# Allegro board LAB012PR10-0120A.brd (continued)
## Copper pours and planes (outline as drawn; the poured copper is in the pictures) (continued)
B+ on TOP (solid shape): 80.73,20.27 80.73,18.67 80.52,18.47 79.04,18.47 78.33,19.17 78.33,20.66 78.62,20.95 80.05,20.95
B+ on TOP (solid shape): 8.45,79.5 8.45,78.58 8.62,78.41 9.33,78.41 10.19,77.55 10.19,76.36 9.95,76.12 6.93,76.12 6.79,76.26 6.79,78.03 6.6,78.21 6.6,78.64 7.16,78.64 7.16,79.13 6.6,79.13 6.6,79.63 6.66,79.68 8.27,79.68
B+ on TOP (solid shape): outline of 233 points within 26.09,18.5 87.59,40.89
B+ on BOTTOM (solid shape): 57.73,25.76 57.73,16.43 57.66,16.36 53.78,16.36 52.97,17.17 52.97,26.66 53.35,27.03 56.46,27.03
B+ on BOTTOM (solid shape): 58.96,118.17 58.96,115.45 58.65,115.14 55.73,115.14 55.4,115.47 55.4,118.24 55.73,118.57 58.55,118.57
B+ on BOTTOM (solid shape): 172.9,48.32 172.9,46.03 172.4,45.52 170.11,45.52 169.86,45.78 169.86,48.32 170.36,48.82 172.4,48.82
B+ on BOTTOM (solid shape): 9.96,77.78 9.96,76.76 9.56,76.36 7.93,76.36 7.93,78.29 8.06,78.41 9.33,78.41
B+ on BOTTOM (solid shape): 48.32,25.8 48.32,22.15 47.81,21.65 45.52,21.65 44.86,22.31 44.86,25.72 45.21,26.06 48.05,26.06
B+ on BOTTOM (solid shape): 80.7,21.39 80.7,18.6 80.57,18.47 78.92,18.47 78.8,18.6 78.8,21.39 78.92,21.52 80.57,21.52
B+ on BOTTOM (solid shape): outline of 149 points within 84.18,34.98 172.68,71.52
B+ on BOTTOM (solid shape): outline of 200 points within 26.22,20.1 32.95,33.84
B+_1.05V on BOTTOM (solid shape): 177.35,54.41 177.35,53.93 177.55,53.73 179.1,53.73 179.25,53.57 179.25,52.38 179.63,52 179.63,50.22 179.51,50.09 177.6,50.09 177.58,50.12 177.58,51.62 176.61,52.58 173.67,52.58 172.83,51.74 172.83,50.93 172.75,50.86 170.87,50.86 170.77,50.96 170.77,52.43 170.94,52.6 171.64,52.6 173.47,54.44 177.32,54.44
BATT+ on TOP (solid shape): 25.33,30.92 25.33,25.33 24.95,24.95 21.14,24.95 20.38,25.71 20.38,30.66 20.5,30.79 21.14,30.79 21.65,31.3 24.95,31.3
BATT+ on BOTTOM (solid shape): 25.33,30.79 25.33,25.2 25.08,24.95 21.27,24.95 20.5,25.71 20.5,30.28 21.52,31.3 24.82,31.3
BATT+ on IN1 (solid shape): 24.57,30.79 24.57,25.46 24.06,24.95 21.14,24.95 20.38,25.71 20.38,30.66 20.5,30.79 21.14,30.79 21.65,31.3 24.06,31.3
BATT++ on TOP (solid shape): 19.87,30.66 19.87,25.33 19.36,24.82 16.06,24.82 15.17,25.71 13.77,25.71 13.65,25.84 13.65,30.15 13.9,30.41 16.69,30.41 17.07,30.79 19.74,30.79
BATT++ on BOTTOM (solid shape): 19.87,30.66 19.87,25.33 19.61,25.07 15.8,25.07 15.17,25.71 13.77,25.71 13.65,25.84 13.65,30.15 13.9,30.41 16.69,30.41 17.07,30.79 19.74,30.79
BATT++ on IN1 (solid shape): 19.87,30.66 19.87,25.33 19.36,24.82 16.06,24.82 15.17,25.71 13.77,25.71 13.65,25.84 13.65,30.15 13.9,30.41 16.69,30.41 17.07,30.79 19.74,30.79
BOOT1 on BOTTOM (solid shape): 58.35,42.09 58.35,40.7 59.37,39.68 59.75,39.68 59.87,39.55 59.87,38.79 59.75,38.66 59.49,38.66 57.33,40.82 57.33,42.09 57.46,42.22 58.22,42.22
BOOT2 on BOTTOM (solid shape): 66,41.97 66,40.29 64.5,38.79 63.58,38.79 63.4,38.61 63.28,38.61 63.2,38.69 63.2,39.58 63.29,39.67 64.03,39.67 64.04,39.65 64.55,39.65 65.16,40.26 65.16,41.05 64.73,41.48 64.73,42.19 64.85,42.32 65.64,42.32
BOOT_1.35V on BOTTOM (solid shape): 89.59,11.1 89.59,10.22 89.46,10.09 87.31,10.09 87.05,10.34 87.05,10.85 86.8,11.1 85.15,11.1 85.15,11.36 89.34,11.36
BST on BOTTOM (solid shape): 44.56,18.32 44.56,16.75 44.23,16.42 44.23,15.47 44.2,15.45 44.08,15.45 44.02,15.5 44.02,17.35 43.69,17.68 43.69,18.39 44.48,18.39
BST_1.05V on BOTTOM (solid shape): 182.81,52.13 182.81,51.36 182.68,51.24 181.92,51.24 181.29,50.6 180.4,50.6 180.27,50.73 180.27,51.11 181.41,52.25 182.68,52.25
BST_1.35V on BOTTOM (solid shape): 89.59,13.64 89.59,11.74 89.46,11.61 88.58,11.61 88.45,11.74 88.45,13.64 88.58,13.77 89.46,13.77
BST_3V on TOP (solid shape): 71.92,21.82 71.92,20.43 71.91,20.39 71.87,20.38 71.56,20.38 71.56,20.38 71.16,20.38 70.96,20.58 70.96,21.79 71.03,21.86 71.88,21.86
BST_5V on TOP (solid shape): 71.63,15.93 71.67,15.92 71.68,15.88 71.68,15.68 71.43,15.42 71.43,15.42 71.1,15.09 71.1,14.02 71.05,13.97 70.1,13.97 69.94,14.13 69.94,14.63 70.89,15.58 71.22,15.58 71.57,15.93
BST_+1.35VGPUP on BOTTOM (solid shape): 33.84,45.39 33.84,44.63 34.73,43.74 34.73,43.11 34.6,42.98 33.71,42.98 32.95,43.74 32.95,45.39 33.08,45.52 33.71,45.52
BST_CHGA on BOTTOM (solid shape): 44.58,19.71 44.58,19.13 44.56,19.11 41.92,19.11 41.89,19.13 41.89,19.77 41.94,19.82 44.48,19.82
CHG_B+ on TOP (solid shape): 47.67,34.99 47.67,30.99 46.88,30.2 44.46,30.2 44.13,30.54 44.13,32.57 43.87,32.82 38.28,32.82 37.52,32.06 37.52,30.79 37.27,30.54 36.89,30.54 36.76,30.66 36.76,37.77 37.14,38.16 44.51,38.16
CHG_B+ on BOTTOM (solid shape): 46.67,34.32 46.67,31.25 45.76,30.34 43.81,30.34 42.73,31.42 42.73,34.01 43.25,34.54 46.45,34.54
DCIN on BOTTOM (solid shape): 49.76,18.27 49.76,17.38 48.93,16.54 48.93,15.52 48.52,15.12 47.76,15.12 47.17,14.53 45.78,14.53 45.65,14.66 45.65,14.79 45.73,14.86 46.63,14.86 47.3,15.54 47.3,16.82 48.88,18.39 49.64,18.39
DH_1.35V on TOP (solid shape): 88.91,13.11 88.91,12.4 87.99,11.49 87.18,11.49 87.05,11.61 87.05,12.18 88.06,13.19 88.83,13.19
DH_1.35V on BOTTOM (solid shape): 88.19,12.12 88.19,11.61 88.07,11.49 85.15,11.49 85.15,11.74 86.92,11.74 87.43,12.25 88.07,12.25
DH_CHG on TOP (solid shape): 43.74,32.06 43.74,29.77 43.62,29.65 42.98,29.65 42.73,29.9 42.73,32.06 42.86,32.19 43.62,32.19
DH_CHG on BOTTOM (solid shape): 43.87,17.28 43.87,15.5 43.8,15.42 43.64,15.42 43.57,15.5 43.57,16.87 42.98,17.45 42.98,17.66 43.14,17.81 43.34,17.81
DH_CHG on IN1 (solid shape): 44,30.41 44,29.77 43.62,29.39 43.24,29.39 42.47,30.15 42.47,30.92 42.6,31.04 43.36,31.04
DH_CHG on IN1 (solid shape): 44.25,18.85 44.25,17.2 44,16.95 43.36,16.95 42.98,17.33 42.98,18.85 43.11,18.98 44.13,18.98
DL_1.35V on BOTTOM (solid shape): 88.45,21.01 88.45,20.12 88.32,19.99 87.43,19.99 87.31,20.12 87.31,21.01 87.43,21.14 88.32,21.14
DL_1.35V on BOTTOM (solid shape): 86.04,14.41 86.04,13.39 84.89,12.25 84.77,12.25 84.64,12.37 84.64,13.39 85.78,14.53 85.91,14.53
DL_1.35V on IN2 (solid shape): 86.16,14.41 86.16,14.03 85.4,13.26 85.02,13.26 84.89,13.39 84.89,14.03 85.53,14.66 85.91,14.66
DL_1.35V on IN2 (solid shape): 88.7,21.26 88.7,20.07 88.5,19.87 87.53,19.87 87.31,20.1 87.31,21.26 87.43,21.39 88.58,21.39
DL_CHG on TOP (solid shape): 36.43,25.74 36.43,24.48 36.23,24.28 35.12,24.28 34.82,24.58 34.82,25.68 35.05,25.91 36.26,25.91
DL_CHG on BOTTOM (solid shape): 41.71,16.46 41.71,15.8 42.22,15.3 42.53,15.3 42.6,15.22 42.6,15.04 42.53,14.96 41.41,14.96 41.06,15.31 41.06,15.57 41.09,15.7 41.06,15.83 41.06,16.44 41.23,16.62 41.56,16.62
DL_CHG on IN1 (solid shape): 36.63,25.84 36.63,24.57 36.28,24.21 35.36,24.21 35.34,24.19 34.98,24.19 34.6,24.57 34.6,25.71 34.98,26.09 36.38,26.09
DL_CHG on IN2 (solid shape): 41.97,17.02 41.97,15.3 41.84,15.17 41.08,15.17 40.98,15.27 40.98,15.3 40.82,15.45 40.82,17.07 41.05,17.3 41.69,17.3
DL_CHG on IN2 (solid shape): 36.53,24.85 36.53,24.36 36.05,23.88 36.05,23.27 35.87,23.09 34.78,23.09 34.63,23.25 34.63,24.85 34.8,25.02 34.88,25.02 34.93,25.07 36.3,25.07
DP_VSSR on TOP (solid shape): 75.49,86.29 75.49,85.84 75.49,85.83 75.48,85.82 75.39,85.63 75.48,85.44 75.49,85.42 75.49,85.4 75.49,85.31 75.49,84.2 75.49,84.19 75.48,84.17 75.42,84 75.48,83.83 75.49,83.82 75.49,83.8 75.49,81.46 75.48,81.44 75.47,81.43 75.34,81.21 75.47,80.99 75.48,80.98 75.49,80.96 75.49,79.3 75.49,79.27 75.47,79.26 75.37,79.05 75.47,78.84 75.49,78.82 75.49,78.8 75.49,78.16 75.24,77.91 72.45,77.91 72.36,78 72.33,78.07 72.35,78.14 72.35,78.49 71.99,78.5 71.92,78.47 71.85,78.5 71.81,78.54 71.81,78.92 71.94,79.05 72.29,79.05 73.01,79.05 73.21,79.05 73.46,79.3 73.46,81.46 73.21,81.72 72.45,81.72 72.32,81.59 72.32,81.21 72.19,81.08 72.09,81.08 71.68,81.08 71.56,81.21 71.56,82.22 71.81,82.48 71.81,84.89 72.45,85.53 72.45,86.42 72.57,86.54 75.24,86.54
EN_PCIE on BOTTOM (solid shape): 76.64,56.19 76.64,55.55 76.76,55.43 77.4,55.43 77.78,55.05 77.78,54.67 77.65,54.54 75.88,54.54 75.37,55.05 74.99,55.05 74.86,55.17 74.86,56.19 74.99,56.32 76.51,56.32
GPU_B+ on TOP (solid shape): 71.38,45.16 74.09,45.16 74.67,44.58 74.67,43.05 73.78,42.16 67.18,42.16 66.48,42.85 61.86,42.85 61.7,42.7 60.43,42.7 60.2,42.47 60.2,41.52 60.1,41.42 58.48,41.42 58.41,41.45 58.38,41.52 58.1,41.79 57.82,41.52 57.79,41.45 57.71,41.42 57.14,41.42 57.13,41.42 56.98,41.46 56.82,41.42 56.81,41.42 56.46,41.42 56.45,41.42 56.32,41.44 56.19,41.42 56.18,41.42 51.95,41.42 51.49,41.87 51.49,45.06 51.56,45.12 51.66,45.32 51.64,45.55 51.63,45.56 51.64,45.6 52.11,46.07 57.13,46.07 57.21,46.16 64.45,46.16 64.7,46.41 64.7,47.17 64.95,47.43 69.12,47.43
GPU_B+ on BOTTOM (solid shape): 66.2,45.92 66.2,44.49 65.69,43.97 57.21,43.97 56.95,44.23 56.95,45.9 57.21,46.16 65.97,46.16
INT-SPK-L+ on TOP (solid shape): 202.04,20.71 202.04,20.2 202.04,20.2 202.04,19.94 202.55,19.44 203.76,19.44 203.92,19.28 203.92,18.5 203.74,18.32 202.04,18.32 200.97,19.38 200.97,20.3 200.95,20.33 200.95,20.91 201.1,21.06 201.68,21.06
INT-SPK-L+ on BOTTOM (solid shape): 201.73,20.6 201.73,19.94 201.33,19.54 199.17,19.54 199.12,19.59 199.12,19.74 199.17,19.79 200.72,19.79 201.12,20.2 201.12,20.55 201.28,20.71 201.63,20.71
INT-SPK-L- on TOP (solid shape): 206.05,20.07 206.05,18.57 205.85,18.37 205.01,18.37 204.83,18.55 204.83,19.44 204.35,19.92 202.49,19.92 202.16,20.25 202.16,20.83 202.42,21.09 205.03,21.09
INT-SPK-L- on BOTTOM (solid shape): 203.87,20.76 203.87,20.3 203.66,20.1 202.9,20.1 201.94,19.13 201.48,19.13 201.43,19.18 199.17,19.18 199.12,19.23 199.12,19.36 199.14,19.38 201.38,19.38 202.11,20.12 202.11,20.4 202.62,20.91 203.71,20.91
INT-SPK-R+ on TOP (solid shape): 209.1,19.31 209.1,18.52 208.9,18.32 206.43,18.32 206.23,18.52 206.23,19.21 206.48,19.46 208.95,19.46
INT-SPK-R+ on BOTTOM (solid shape): 201.28,18.17 201.28,17.5 201.22,17.45 200.95,17.45 200.59,17.81 200.59,18.19 200.41,18.37 199.19,18.37 199.12,18.44 199.12,18.55 199.17,18.6 200.84,18.6
INT-SPK-R+ on IN2 (solid shape): 207.93,19.16 207.93,18.55 207.75,18.37 202.47,18.37 202.44,18.34 201.86,18.34 201.45,17.94 201.45,17.76 201.48,17.73 201.48,17.33 201.33,17.17 200.59,17.17 200.39,17.38 200.39,19.18 200.41,19.18 200.64,19.41 207.68,19.41
INT-SPK-R- on TOP (solid shape): 212.88,19.44 212.88,18.77 212.48,18.37 210.11,18.37 209.91,18.57 209.91,19.38 210.11,19.59 212.73,19.59
INT-SPK-R- on BOTTOM (solid shape): 202.44,18.01 202.44,16.95 202.29,16.79 201.99,16.79 201.81,16.97 201.81,17.89 200.92,18.77 199.17,18.77 199.12,18.83 199.12,18.95 199.17,19 201.1,19 201.15,19.05 201.4,19.05
INT-SPK-R- on IN2 (solid shape): 213.06,19.36 213.06,18.83 212.78,18.55 211.51,18.55 209.78,16.82 202.65,16.82 202.56,16.74 201.9,16.74 201.69,16.95 201.69,17.68 202.08,18.06 209.45,18.06 211.03,19.64 212.78,19.64
KB_BL_PWM on TOP (solid shape): 121.16,13.85 121.16,13.19 122.23,12.12 122.23,8.16 121.3,7.23 120.63,7.23 120.45,7.41 120.45,10.62 119.44,11.64 119.44,13.9 119.56,14.03 120.99,14.03
LG_3V on TOP (solid shape): 69.69,19.93 69.69,19.92 70.59,19.03 71.22,19.03 71.29,18.97 71.29,18.9 71.22,18.84 69.93,18.84 68.91,19.85 68.91,20.16 69.04,20.29 69.34,20.29
LG_5V on TOP (solid shape): 63.73,17.38 63.73,16.62 63.68,16.57 63.68,16.06 63.18,15.55 62.54,15.55 62.29,15.8 62.29,16.95 62.3,16.96 62.3,17.42 62.46,17.59 63.52,17.59
LG_5V on TOP (solid shape): 71.29,17.39 71.29,17.25 71.22,17.19 70.84,17.19 70.45,16.79 70.45,16.46 69.9,15.92 69.47,15.92 69.37,16.02 69.37,16.3 69.37,16.32 69.38,16.33 69.42,16.38 69.46,16.44 70.23,17.21 70.22,17.23 70.22,17.33 70.33,17.44 71.24,17.44
LG_5V on IN1 (solid shape): 70.54,16.82 70.54,16.31 69.65,15.42 69.4,15.42 69.02,15.8 69.02,16.06 70.03,17.07 70.29,17.07
LG_5V on IN1 (solid shape): 63.23,16.7 63.23,16.26 63.81,15.68 63.81,15.42 63.43,15.04 63.05,15.04 62.36,15.73 62.36,16.78 62.44,16.86 63.07,16.86
LG_+1.35VGPUP on TOP (solid shape): 41.51,49.37 41.51,48.78 41.31,48.57 39.88,48.57 39.68,48.77 39.68,49.59 39.81,49.71 41.17,49.71
LGATE on TOP (solid shape): 85.58,119 85.58,118.55 85.35,118.32 84.33,118.32 84.13,118.52 84.13,119.46 84.21,119.54 85.05,119.54
LGATE on TOP (solid shape): 73.25,112.78 73.25,112.58 72.05,111.39 72.05,111.22 72.02,111.18 71.3,111.18 71.27,111.22 71.27,111.91 72.18,112.83 73.2,112.83
LGATE on BOTTOM (solid shape): 85.4,118.93 85.4,117.91 85.27,117.78 84.38,117.78 84.26,117.91 84.26,119.05 84.38,119.18 85.15,119.18
LGATE1 on TOP (solid shape): 60.38,54.87 60.38,54.16 60.64,53.9 60.64,53.52 60.51,53.4 59.37,53.4 59.11,53.65 59.11,53.9 59.29,54.08 59.59,54.08 59.75,54.23 59.75,54.87 59.85,54.97 60.28,54.97
LGATE1 on BOTTOM (solid shape): 61.4,42.47 61.4,41.46 61.02,41.08 61.02,38.66 60.89,38.66 60.76,38.79 60.76,40.82 60.25,41.33 60.25,42.47 60.38,42.6 61.27,42.6
LGATE1 on IN2 (solid shape): 61.22,42.47 61.22,41.43 60.97,41.18 60.64,41.18 60.33,41.48 60.33,42.47 60.51,42.65 61.04,42.65
LGATE1 on IN2 (solid shape): 60.69,53.84 60.69,53.17 60.48,52.96 59.8,52.96 59.71,53.05 59.71,53.14 59.26,53.59 59.26,53.93 59.41,54.08 60.45,54.08
LGATE2 on TOP (solid shape): 62.79,48.68 62.79,48.24 63.07,47.96 63.07,47.63 62.95,47.5 62.06,47.5 61.91,47.65 61.91,48.62 62.02,48.73 62.74,48.73
LGATE2 on BOTTOM (solid shape): 62.92,42.6 62.92,40.7 62.29,40.06 62.29,38.79 62.16,38.66 62.03,38.79 62.03,40.31 62.29,40.57 62.29,41.46 61.78,41.97 61.78,42.6 61.91,42.73 62.79,42.73
LGATE2 on IN2 (solid shape): 63.07,48.02 63.07,47.35 62.9,47.17 61.78,47.17 61.65,47.3 61.65,47.91 62.02,48.29 62.81,48.29
LX_1.05V on BOTTOM (solid shape): 183.19,53.9 183.19,53.65 182.81,53.27 182.81,52.63 182.68,52.51 182.05,52.51 181.92,52.63 181.92,53.85 182.1,54.03 183.06,54.03
LX_1.05V on BOTTOM (solid shape): 179.63,47.81 180.65,46.79 180.65,44.51 180.02,43.87 176.59,43.87 175.57,42.85 173.41,42.85 173.16,43.11 173.16,44.38 173.67,44.89 174.94,44.89 176.9,46.85 177.54,46.85 178.49,47.81 178.49,48.95 179.63,48.95
LX_1.8VSP on BOTTOM (solid shape): 87.28,28.76 87.28,27.18 86.97,26.88 86.97,25.73 86.92,25.68 86.8,25.68 86.72,25.76 86.72,26.09 86.72,26.42 86.47,26.67 86.24,26.67 86.14,26.57 86.13,26.57 85.83,26.28 85.64,26.09 85.64,25.83 85.01,25.83 85.01,26.72 84.75,26.97 83.54,26.97 83.37,27.14 83.37,28.76 83.5,28.88 87.15,28.88
LX_3V on TOP (solid shape): 66.35,26.93 66.35,23.3 63.25,23.3 63.19,23.36 63.19,23.37 62.02,24.54 60.46,24.54 60.27,24.73 60.27,27.31 60.28,27.31 60.53,27.56 65.72,27.56
LX_3V on TOP (solid shape): 73.69,21.73 73.69,21.26 73.54,21.1 73.36,21.1 72.37,20.11 72.37,19.16 72.3,19.09 72.24,19.09 72.18,19.16 72.18,20.3 72.05,20.43 72.05,21.32 72.18,21.44 72.18,21.45 72.59,21.86 73.56,21.86
LX_3V on BOTTOM (solid shape): 65.33,26.4 65.33,21.14 65.21,21.01 61.14,21.01 60.61,21.54 60.61,26.64 60.86,26.89 64.85,26.89
LX_3V on IN1 (solid shape): 63.56,24.69 63.56,24.06 64.06,23.55 64.06,23.42 63.81,23.17 63.43,23.17 62.92,23.68 62.92,24.69 63.05,24.82 63.43,24.82
LX_3V on IN1 (solid shape): 72.56,21.63 72.56,20.43 72.43,20.3 72.08,20.3 71.73,20.65 71.73,21.38 71.44,21.67 71.44,21.95 71.7,22.2 71.99,22.2
LX_5V on TOP (solid shape): 72.37,17.07 72.37,15.91 72.56,15.73 72.56,14.94 72.33,14.71 72.33,14.18 72.21,14.05 71.42,14.05 71.3,14.17 71.3,15.04 72.11,15.85 72.11,16.99 72.22,17.1 72.35,17.1
LX_5V on TOP (solid shape): 65.69,15.32 65.69,13.64 65.72,13.62 65.72,13.14 65.59,13.01 65.33,13.01 65.21,12.88 65.21,10.85 64.32,9.96 61.52,9.96 59.52,11.97 59.52,13.92 59.75,14.15 61.14,14.15 61.22,14.08 61.22,12.04 61.4,11.87 62.67,11.87 62.85,12.04 62.85,12.63 63.3,13.08 63.3,15.3 63.3,15.3 63.43,15.42 65.59,15.42
LX_5V on BOTTOM (solid shape): outline of 87 points within 59.37,10.09 65.7,15.17
LX_5V on IN1 (solid shape): 72.81,15.79 72.81,14.39 72.45,14.03 71.94,14.03 71.54,14.42 71.54,15.73 71.8,15.98 72.62,15.98
LX_5V on IN1 (solid shape): 65.84,12.76 65.84,12.12 65.72,11.99 64.57,11.99 64.32,11.74 62.92,11.74 62.79,11.87 62.79,12.37 63.3,12.88 65.72,12.88
LX_CHG on TOP (solid shape): 42.22,31.81 42.22,29.9 42.98,29.14 42.98,25.46 42.73,25.2 37.39,25.2 37.01,25.58 37.01,29.39 38.92,31.3 38.92,31.93 39.05,32.06 41.97,32.06
LX_CHG on BOTTOM (solid shape): 42.09,31.55 42.09,29.9 42.73,29.27 42.73,23.73 42.2,23.19 38.77,23.19 37.88,24.08 37.88,24.79 37.9,24.82 37.9,30.28 38.54,30.92 40.24,30.92 41,31.68 41.97,31.68
LX_CHG on BOTTOM (solid shape): 42.78,18.27 42.78,17.43 43.44,16.77 43.44,15.5 43.39,15.45 43.26,15.45 43.19,15.52 43.19,16.44 43.08,16.54 42.75,16.54 41.87,17.43 41.87,18.29 41.92,18.34 42.7,18.34
LX_CHG on IN1 (solid shape): 43.24,16.82 43.24,16.57 42.98,16.31 42.47,16.31 41.33,17.45 41.33,18.22 41.46,18.34 41.71,18.34
LX_CHG on IN1 (solid shape): 42.65,29.67 42.65,27.31 42.73,27.23 42.73,25.2 42.47,24.95 41.33,24.95 41.2,25.07 41.05,25.07 40.72,25.4 40.72,29.04 40.47,29.29 38.59,29.29 37.98,29.9 37.98,31.07 38.16,31.25 41.08,31.25
LX_PCIE on TOP (solid shape): 76.64,59.49 76.64,57.36 76.38,57.1 74.53,57.1 74.1,56.67 74.1,55.17 73.97,55.05 72.7,55.05 72.45,55.3 72.45,55.58 71.15,56.87 71.15,59.21 71.68,59.75 76.38,59.75
LX_PCIE on BOTTOM (solid shape): 76.49,59.47 76.49,57.36 75.83,56.7 74.35,56.7 74.1,56.44 74.1,55.17 73.97,55.05 72.19,55.05 72.07,55.17 72.07,55.99 71.15,56.9 71.15,59.19 71.71,59.75 76.21,59.75
MIC_IN_R on IN2 (solid shape): 198.56,34.21 199.42,34.21 199.66,33.96 199.66,32.81 199.48,32.63 197.61,32.63 197.16,33.08 197.16,33.81 197.58,33.82 197.7,34.22 198.56,34.22
PACIN# on TOP (solid shape): 77.78,97.72 77.78,96.83 77.65,96.7 76.13,96.7 76,96.83 76,97.85 76.13,97.97 77.53,97.97
PCIE_B+ on BOTTOM (solid shape): 74.1,52.76 74.1,51.87 74.99,50.98 76.13,50.98 76.26,51.11 76.26,52.38 76.51,52.63 77.53,52.63 77.65,52.51 77.65,49.2 77.4,48.95 73.46,48.95 73.34,49.08 73.34,51.11 72.83,51.62 72.83,52.76 72.95,52.89 73.97,52.89
PHASE on TOP (solid shape): 74.22,111.69 74.22,111.05 74.1,110.93 72.95,110.93 72.83,110.8 72.45,110.8 72.32,110.67 71.29,110.67 71.25,110.71 71.25,110.89 71.29,110.93 72.07,110.93 72.95,111.82 74.1,111.82
PHASE on BOTTOM (solid shape): 79.94,118.29 79.94,117.91 79.69,117.66 79.05,117.66 78.29,116.9 77.78,116.9 77.65,117.02 77.65,117.4 78.8,118.55 79.69,118.55
PHASE on IN2 (solid shape): 78.86,117.91 78.86,117.53 78.1,116.77 77.84,116.77 77.46,117.15 78.35,118.04 78.73,118.04
PHASE on IN2 (solid shape): 73.46,111.92 73.46,111.56 72.7,110.8 72.45,110.8 72.32,110.93 72.32,111.71 72.7,112.09 73.29,112.09
PHASE1 on TOP (solid shape): 54.91,56.31 55.02,56.29 55.13,56.31 55.14,56.32 55.56,56.32 56.45,55.42 56.45,46.93 56.14,46.63 53.3,46.63 52.92,47.01 52.92,48.48 52.62,48.78 51.98,48.78 50.71,50.04 50.27,50.04 50.09,50.22 50.09,54.41 52,56.32 54.9,56.32
PHASE1 on BOTTOM (solid shape): 60,42.22 60,41.2 60.64,40.57 60.64,38.66 60.56,38.59 60.48,38.59 60.41,38.66 60.41,40.03 59.75,40.7 59.7,40.7 58.98,41.41 58.98,42.22 59.11,42.35 59.87,42.35
PHASE1 on BOTTOM (solid shape): outline of 186 points within 49.36,45.97 57.46,59.49
PHASE1 on IN2 (solid shape): 51.64,51.41 51.64,50.12 51.5,49.98 51.02,49.98 50.88,50.12 50.88,51.31 51.01,51.44 51.62,51.44
PHASE1 on IN2 (solid shape): 60,41.97 60,41.58 60.64,40.95 60.64,40.42 60.38,40.16 60.15,40.16 59.11,41.2 59.11,41.46 58.86,41.71 58.86,42.09 59.11,42.35 59.62,42.35
PHASE2 on TOP (solid shape): 71.56,54.74 71.56,52.51 71.56,52.5 71.56,50.92 71.87,50.61 73.48,50.61 73.58,50.51 73.58,49.31 73.49,49.22 73.22,49.22 73.21,49.22 71.56,49.22 70.53,48.19 66.35,48.19 66.1,48.44 66.1,49.72 65.6,50.22 64.93,50.22 64.7,50.45 64.7,54.46 65.23,55 71.3,55
PHASE2 on BOTTOM (solid shape): 64.19,42.22 64.19,41.08 63.68,40.57 63.35,40.57 62.67,39.88 62.67,38.66 62.41,38.66 62.41,39.93 63.05,40.57 63.05,42.22 63.18,42.35 64.06,42.35
PHASE2 on BOTTOM (solid shape): 63.89,59.49 63.92,59.48 63.94,59.44 63.94,58.76 63.94,56.29 64.7,56.29 64.7,58.76 64.7,59.44 64.71,59.48 64.75,59.49 65.84,59.49 68.89,56.44 68.89,56.42 69,56.17 69.25,56.06 69.27,56.06 69.53,55.81 71.05,55.81 71.3,55.55 71.3,48.92 71.2,48.82 65.17,48.82 64.73,49.27 64.73,53.57 64.57,53.73 62.48,53.73 62.29,53.92 62.29,59.36 62.41,59.49
PHASE2 on IN1 (solid shape): 64.32,41.58 64.32,41.33 63.56,40.57 63.3,40.57 62.92,40.95 62.92,41.2 63.68,41.97 63.94,41.97
PHASE2 on IN1 (solid shape): 71,49.22 71,48.67 70.87,48.54 69.48,48.54 69.41,48.61 69.41,49.29 69.49,49.37 70.85,49.37
PWR_SRC_ON on TOP (solid shape): 10.09,75.87 10.09,75.44 9.99,75.34 9.33,75.34 9.18,75.19 9.18,73.87 8.87,73.56 7.02,73.56 6.76,73.82 6.76,75.67 7.07,75.98 9.99,75.98
RING2_R on IN2 (solid shape): 197.74,32.11 197.74,31.12 197.67,31.04 196.4,31.04 196.07,31.37 196.07,32.85 196.14,32.92 196.93,32.92
RING2_R on IN2 (solid shape): 200.42,38.36 203.18,38.36 203.33,38.51 207.82,38.51 208.04,38.4 208.27,38.37 209.42,38.37 210.39,37.39 210.39,36.73 210.27,36.61 208.69,36.61 208.69,36.63 208.11,37.22 208.11,37.22 207.98,37.34 206.75,37.34 206.55,37.48 206.3,37.53 205.39,37.53 205.14,37.48 204.94,37.34 202.65,37.34 202.45,37.48 202.2,37.53 201.29,37.53 201.04,37.48 200.84,37.34 199.55,37.34 199.35,37.55 199.35,38.59 199.45,38.69 200.09,38.69
SNB_1.05V on BOTTOM (solid shape): 175.32,46.66 175.32,45.65 175.19,45.52 173.41,45.52 173.16,45.78 173.16,47.55 173.28,47.68 174.3,47.68
SNUB_PCIE on TOP (solid shape): 76.64,56.48 76.64,54.7 76.51,54.58 76.24,54.58 76.12,54.7 76.12,55.31 75.88,55.55 74.73,55.55 74.61,55.68 74.61,56.57 74.76,56.72 75.09,56.72 75.1,56.74 76.38,56.74
SPK_L1-_CONN on TOP (solid shape): 205.97,17.81 205.97,15.7 206.23,15.45 206.23,15.07 205.9,14.74 205.44,14.74 204.88,15.3 204.88,17.86 204.93,17.91 205.87,17.91
SPK_L1-_CONN on BOTTOM (solid shape): 206.18,19.36 206.18,15.68 206.56,15.3 206.56,13.26 206.3,13.01 205.92,13.01 205.67,13.26 205.67,14.91 205.03,15.55 205.03,18.22 204.78,18.47 204.78,19.61 205.03,19.87 205.67,19.87
SPK_L2+_CONN on TOP (solid shape): 203.97,17.81 203.97,15.24 204.53,14.69 204.53,14.03 204.25,13.75 203.82,13.75 202.85,14.71 202.85,17.84 202.93,17.91 203.87,17.91
SPK_L2+_CONN on BOTTOM (solid shape): 204.02,19.49 204.02,18.47 203.76,18.22 203.76,15.68 204.4,15.04 205.03,15.04 205.29,14.79 205.29,13.26 205.03,13.01 204.65,13.01 202.62,15.04 202.62,19.23 203.26,19.87 203.64,19.87
SPK_R1-_CONN on TOP (solid shape): 211.11,17.81 211.11,16.87 211.08,16.85 211.08,16.03 211.11,16.01 211.11,15.7 211.33,15.47 211.33,14.08 211,13.75 210.52,13.75 209.96,14.3 209.96,17.86 210.04,17.94 210.98,17.94
SPK_R1-_CONN on BOTTOM (solid shape): 211,19.61 211,18.72 211.38,18.34 211.38,14.66 209.73,13.01 208.34,13.01 208.21,13.14 208.21,14.66 208.46,14.91 209.73,14.91 210.37,15.55 210.37,17.45 209.73,18.09 209.73,19.36 210.11,19.74 210.88,19.74
SPK_R2+_CONN on TOP (solid shape): 208.97,17.91 208.97,15.63 208.26,14.91 207.45,14.91 207.22,15.14 207.22,15.65 207.63,16.06 207.63,16.97 207.63,17.91 207.7,17.99 208.9,17.99
SPK_R2+_CONN on BOTTOM (solid shape): 209.1,19.49 209.1,17.96 208.72,17.58 208.72,15.68 207.83,14.79 207.83,13.39 207.45,13.01 207.19,13.01 206.94,13.26 206.94,15.3 207.57,15.93 207.57,17.96 207.96,18.34 207.96,19.49 208.21,19.74 208.84,19.74
SW_1.35V on BOTTOM (solid shape): 87.81,13.52 87.81,12.76 87.69,12.63 87.43,12.63 86.67,11.87 85.15,11.87 85.15,12.25 85.65,12.25 87.05,13.64 87.69,13.64
SW_1.35V on BOTTOM (solid shape): 94.8,20.63 94.8,15.93 93.86,14.99 90.4,14.99 90.4,14.99 90.36,14.99 90.04,15.31 90.04,17.08 89.03,18.09 89.03,21.98 89.21,22.15 93.27,22.15
SW_1.35V on IN2 (solid shape): 91.52,17.63 91.52,16.59 86.8,11.87 86.29,11.87 86.16,11.99 86.16,13.52 86.35,13.71 87.06,13.71 90.33,16.97 90.33,17.35 90.73,17.76 91.4,17.76
SW_+1.35VGPUP on TOP (solid shape): 37.78,51.49 37.78,50.86 39.17,49.46 39.17,46.66 39.43,46.41 40.7,46.41 41.08,46.03 41.08,44 40.95,43.87 39.3,43.87 38.28,44.89 37.14,44.89 37.01,45.01 37.01,46.03 36.76,46.28 36.63,46.28 36.63,47.83 35.58,48.88 35.58,50.91 36.12,51.45 36.12,51.49 36.38,51.74 37.52,51.74
SW_+1.35VGPUP on BOTTOM (solid shape): 40.82,47.68 40.82,43.87 39.81,42.85 37.01,42.85 36.63,43.24 36.63,45.14 36.38,45.39 35.36,45.39 34.6,46.16 32.95,46.16 32.95,46.54 36.25,46.54 36.63,46.92 36.63,47.55 37.27,48.19 40.32,48.19
SW_CPU2 on TOP (solid shape): 90.73,118.8 90.73,113.06 90.53,112.86 85.4,112.86 85.1,113.16 85.1,116.97 86.04,117.91 86.04,119.69 86.29,119.94 89.59,119.94
SW_CPU2 on BOTTOM (solid shape): 87.25,120.02 87.43,119.97 87.62,120.02 89.52,120.02 90.73,118.8 90.73,116.39 88.4,116.39 88.4,115.63 90.73,115.63 90.73,112.42 90.25,111.94 84.56,111.94 84.26,112.25 84.26,116.9 84.51,117.15 85.27,117.15 86.04,117.91 86.04,119.84 86.21,120.02
SW_CPU2 on IN1 (solid shape): 90.73,118.8 90.73,111.82 90.23,111.31 84.64,111.31 84.26,111.69 84.26,116.9 84.51,117.15 85.27,117.15 86.04,117.91 86.04,119.69 86.29,119.94 89.59,119.94
SW_CPU2 on IN2 (solid shape): 90.73,118.8 90.73,116.39 88.4,116.39 88.4,115.63 90.73,115.63 90.73,111.82 90.23,111.31 84.64,111.31 84.26,111.69 84.26,116.9 84.51,117.15 85.27,117.15 86.04,117.91 86.04,119.69 86.29,119.94 89.59,119.94
UG_3V on TOP (solid shape): 60.1,25.48 60.1,24.72 59.91,24.53 59.18,24.53 59.09,24.63 59.09,25.54 59.21,25.67 59.91,25.67
UG_3V on TOP (solid shape): 70.97,20.11 71.48,20.11 71.48,20.11 71.53,20.11 71.58,20.06 71.58,19.14 71.53,19.09 71.43,19.09 71.37,19.16 70.84,19.16 70.06,19.94 70.06,20.21 70.33,20.49 70.59,20.49
UG_3V on IN1 (solid shape): 71.29,19.96 71.29,19.36 71.15,19.22 70.88,19.22 69.32,20.78 69.32,20.95 69.75,21.38 69.87,21.38
UG_3V on IN1 (solid shape): 59.91,25.68 59.91,23.71 59.75,23.55 58.98,23.55 58.83,23.71 58.83,25.74 59.02,25.93 59.65,25.93
UG_5V on TOP (solid shape): 71.63,17.06 71.63,16.17 71.19,15.73 70.87,15.73 70.7,15.9 70.7,16.85 70.91,17.06 71.28,17.06 71.35,17.14 71.56,17.14
UG_5V on TOP (solid shape): 62.67,13.9 62.67,12.25 62.54,12.12 61.55,12.12 61.44,12.23 61.44,13.94 61.52,14.03 62.54,14.03
UG_5V on IN1 (solid shape): 71.35,16.74 71.35,15.09 71.19,14.93 70.75,14.93 70.51,15.16 70.51,15.84 70.72,16.04 70.72,16.93 70.78,17 71.1,17
UG_5V on IN1 (solid shape): 62.95,13.34 62.95,13.14 62.67,12.86 62.67,12.25 62.54,12.12 62.36,12.12 62.36,12.12 61.73,12.12 61.72,12.12 61.58,12.12 61.47,12.22 61.47,13.39 61.72,13.64 62.65,13.64
UG_+1.35VGPUP on TOP (solid shape): 36.76,45.9 36.76,45.01 36.63,44.89 34.35,44.89 34.09,45.14 34.09,45.9 34.22,46.03 36.63,46.03
UG_+1.35VGPUP on BOTTOM (solid shape): 34.85,45.52 34.85,45.14 34.6,44.89 34.35,44.89 34.09,45.14 34.09,45.39 33.84,45.65 33.08,45.65 32.95,45.78 32.95,46.03 34.35,46.03
UGATE on TOP (solid shape): 73.46,110.67 73.46,110.42 73.12,110.08 72.28,110.08 72.19,110.16 71.3,110.16 71.27,110.2 71.27,110.38 71.3,110.42 72.35,110.42 72.47,110.55 72.83,110.55 73.08,110.8 73.34,110.8
UGATE on BOTTOM (solid shape): 74.28,110.9 74.28,110.14 74.17,110.04 73.08,110.04 72.74,109.7 72.03,109.7 71.95,109.78 71.95,110.38 72.12,110.55 72.57,110.55 72.95,110.93 74.25,110.93
UGATE1 on TOP (solid shape): 50.98,48.06 50.98,46.28 50.73,46.03 50.22,46.03 49.97,46.28 49.97,48.19 50.09,48.32 50.73,48.32
UGATE1 on BOTTOM (solid shape): 60.25,39.93 60.25,38.66 60.18,38.59 60.08,38.59 60,38.66 60,39.81 59.87,39.93 59.37,39.93 58.48,40.82 58.48,41.08 58.6,41.2 58.98,41.2
UGATE1 on IN2 (solid shape): 51.06,47.76 51.06,46.05 51.01,46 50.39,46 50.12,46.27 50.12,47.76 50.2,47.83 50.98,47.83
UGATE1 on IN2 (solid shape): 58.98,41.33 58.98,41.08 59.49,40.57 59.49,40.31 59.34,40.16 58.83,40.16 57.97,41.03 57.97,41.2 58.48,41.71 58.6,41.71
UGATE2 on TOP (solid shape): 64.95,47.91 64.95,47.61 64.85,47.5 64.22,47.5 64.22,47.5 63.79,47.5 63.63,47.65 63.63,47.93 63.44,48.12 63.44,48.66 63.48,48.7 64.17,48.7
UGATE2 on BOTTOM (solid shape): 65,40.72 65,40.44 64.42,39.86 64.01,39.86 63.96,39.91 63.3,39.91 63.05,39.65 63.05,38.64 63,38.59 62.85,38.59 62.79,38.64 62.79,39.76 63.43,40.39 63.79,40.39 64.32,40.92 64.8,40.92
UGATE2 on IN2 (solid shape): 65,40.57 65,40.36 64.4,39.76 64.04,39.76 63.73,40.06 63.73,40.26 63.89,40.42 63.94,40.42 64.4,40.87 64.7,40.87
VSMB on BOTTOM (solid shape): 44.82,10.03 44.82,9.43 44.71,9.33 44.18,9.33 44,9.15 44,8.13 43.4,7.54 42.17,7.54 42.04,7.66 42.04,8.28 42.1,8.44 42.09,8.6 42.86,9.36 43.39,9.36 43.55,9.53 43.55,10.09 43.63,10.16 44.68,10.16
N16955074 on TOP (solid shape): 59.49,54.79 59.49,54.26 59.44,54.21 58.87,54.21 58.65,53.99 58.65,52.95 58.31,52.62 57.36,52.62 57.11,52.87 57.11,54.79 57.26,54.94 59.34,54.94
N16955074 on BOTTOM (solid shape): 59.2,49.72 59.2,49.02 59.01,48.84 57.28,48.84 57.19,48.93 57.19,49.59 57.32,49.71 58.55,49.71 58.76,49.92 59,49.92
N16955074 on IN1 (solid shape): 58.51,54.37 58.51,53.43 58.38,53.29 56.82,53.29 56.68,53.43 56.68,54.28 56.94,54.54 58.34,54.54
N16955074 on IN1 (solid shape): 58.37,50.01 58.9,50.01 59.09,49.81 59.09,48.96 58.94,48.8 57.93,48.8 57.46,49.28 57.46,50.1 57.57,50.22 58.16,50.22
N16955100 on BOTTOM (solid shape): 55.52,47.96 55.52,46.8 55.75,46.58 56.64,46.58 56.7,46.51 56.7,45.81 56.65,45.76 54.59,45.76 54.27,46.08 54.27,48.07 54.31,48.11 55.37,48.11
N16955117 on BOTTOM (solid shape): 60,43.46 60,42.83 59.92,42.75 57.49,42.75 57.36,42.88 57.36,43.49 57.41,43.54 59.92,43.54
N16955207 on TOP (solid shape): 52.07,48.44 52.51,48.44 52.61,48.34 52.61,46.63 52.49,46.52 51.85,46.52 51.29,47.08 51.29,48.01 50.73,48.57 50.22,48.57 50.09,48.7 50.09,49.33 50.35,49.59 50.92,49.59
N16988653 on BOTTOM (solid shape): 83.86,24.88 83.86,23.67 84.12,23.42 85.64,23.42 85.77,23.29 85.77,23.3 86.54,23.3 86.72,23.47 86.72,24.26 86.75,24.29 86.92,24.29 86.98,24.24 86.98,23.02 85.98,22.02 82.21,22.02 82.02,22.21 82.02,23.04 82.58,23.04 82.59,23.05 82.59,24.41 82.02,24.41 82.02,24.56 82.02,25.01 82.15,25.13 83.61,25.13
N17087943 on BOTTOM (solid shape): 66.1,36.38 66.1,36.12 65.84,35.87 65.59,35.87 65.21,35.49 63.56,35.49 63.43,35.62 63.43,36.5 63.52,36.59 63.54,36.6 63.56,36.61 63.61,36.6 64.42,36.6 64.47,36.61 64.53,36.63 65.84,36.63
N17089248 on BOTTOM (solid shape): 65.33,38.16 65.33,37.78 65.33,37.74 65.3,37.7 65.12,37.52 63.56,37.52 63.43,37.65 63.43,38.03 63.56,38.16 64.83,38.16 64.95,38.28 65.21,38.28
N17258399 on TOP (solid shape): 23.22,116.31 23.22,115.7 25.08,113.85 26.85,113.85 27.33,113.37 27.33,111.81 27.18,111.66 24.03,111.66 22.23,113.47 20.15,113.47 19.74,113.87 19.74,116.44 20.22,116.92 22.61,116.92
N17283470 on TOP (solid shape): 91.4,14 91.4,13.69 90.28,12.58 89.34,12.58 89.31,12.6 89.31,13.31 90.2,14.2 91.19,14.2
N17283470 on BOTTOM (solid shape): 91.37,14.66 91.37,13.64 91.24,13.52 90.1,13.52 89.97,13.64 89.97,14.53 90.23,14.79 91.24,14.79
N17446326 on BOTTOM (solid shape): 37.52,39.04 37.52,38.39 37.52,38.38 36.15,38.38 35.79,38.03 36.15,37.67 37.47,37.67 37.51,37.66 37.52,37.62 37.52,37.01 37.65,36.89 40.06,36.89 40.19,36.76 40.19,35.74 40.06,35.62 34.85,35.62 34.6,35.36 34.6,34.35 34.35,34.09 32.14,34.09 31.76,34.47 31.76,37.03 31.77,37.13 31.76,37.22 31.76,38.92 32.01,39.17 37.39,39.17
N17446342 on BOTTOM (solid shape): 26.71,42.03 26.71,41.56 26.46,41.3 26.46,39.51 26.8,39.17 26.8,38.03 27.06,37.77 29.98,37.77 30.36,37.39 30.36,34.22 30.23,34.09 29.07,34.09 28.72,34.4 28.37,34.09 27.44,34.09 27.18,34.35 27.18,35.23 26.93,35.49 24.95,35.49 24.69,35.74 24.69,38.66 25.71,39.68 25.71,41.95 25.84,42.08 26.66,42.08
N17613161 on BOTTOM (solid shape): 180.27,51.74 180.14,51.62 180.14,50.09 179.76,50.09 179.76,52.13 179.51,52.38 179.51,55.17 179.63,55.3 180.27,55.3
N17613228 on BOTTOM (solid shape): 184.21,53.52 184.21,51.36 184.08,51.24 183.44,51.24 183.32,51.36 183.32,53.52 183.44,53.65 184.08,53.65
N17933209 on TOP (solid shape): 62.73,50.98 63.87,50.98 63.96,50.89 63.96,50.34 63.82,50.2 63.38,50.2 62.91,49.73 62.91,49.24 62.75,49.08 62.15,49.08 62.01,49.21 62.01,50.7 61.96,50.75 61.96,51.18 62.05,51.27 62.45,51.27
N17933209 on BOTTOM (solid shape): 63.98,53.37 63.98,52.85 63.86,52.73 63.13,52.73 62.74,52.34 62.07,52.34 62,52.41 62,53.42 62.09,53.51 62.19,53.51 62.2,53.52 63.83,53.52
N17933209 on IN2 (solid shape): 63.08,53.46 63.08,52.35 62.93,52.19 62.17,52.19 62.03,52.33 62.03,53.38 62.26,53.6 62.94,53.6
N17933209 on IN2 (solid shape): 63.1,50.86 63.1,49.78 62.97,49.65 62.12,49.65 61.99,49.79 61.99,50.83 62.06,50.91 63.05,50.91
N17933219 on TOP (solid shape): 74.86,48.7 74.86,47.92 74.78,47.85 74.09,47.85 73.51,47.27 73.51,46.58 73.42,46.49 71.81,46.49 71.7,46.6 71.7,47.9 71.76,47.96 72.99,47.96 73.83,48.8 74.76,48.8
N17933234 on BOTTOM (solid shape): 65.72,43.62 65.72,42.98 65.59,42.85 63.18,42.85 63.05,42.98 63.05,43.62 63.18,43.74 65.59,43.74
N17933249 on TOP (solid shape): 65.72,49.38 65.72,48.29 65.59,48.16 65.06,48.16 64.67,48.54 64.67,48.9 64.55,49.03 63.48,49.03 63.4,49.1 63.4,49.59 63.51,49.69 63.51,49.69 63.58,49.76 65.34,49.76
N21178712 on TOP (solid shape): 35.74,111.18 35.74,108.64 35.49,108.39 34.22,108.39 34.09,108.51 34.09,109.15 33.71,109.53 32.19,109.53 32.06,109.66 32.06,111.18 32.26,111.38 35.55,111.38
N22753332 on BOTTOM (solid shape): 76.76,110.55 76.76,110.29 76.51,110.04 74.61,110.04 74.56,110.09 74.56,110.62 74.66,110.72 75.55,110.72 75.75,110.93 75.76,110.93 75.88,111.05 76.26,111.05
N22753332 on BOTTOM (solid shape): 79.94,117.02 79.94,116.51 79.81,116.39 79.3,116.39 78.42,115.5 78.03,115.5 77.91,115.63 77.91,116.01 79.05,117.15 79.81,117.15
N22753332 on IN2 (solid shape): 76.76,110.55 76.76,110.29 76.51,110.04 75.75,110.04 75.62,110.16 75.62,110.93 75.75,111.05 76.26,111.05
N22753332 on IN2 (solid shape): 78.92,116.45 78.92,115.94 78.42,115.43 78.16,115.43 77.91,115.69 77.91,115.94 78.54,116.58 78.8,116.58
N22753389 on TOP (solid shape): 75.75,111.69 75.75,111.05 75.49,110.8 75.49,109.02 75.39,108.92 74.71,108.92 74.48,109.15 74.48,111.43 74.86,111.82 75.62,111.82
N22763755 on TOP (solid shape): 18.6,37.39 18.6,36.12 18.34,35.87 15.68,35.87 15.55,36 15.55,37.27 15.68,37.39 16.19,37.39 16.31,37.52 18.47,37.52
N22763755 on BOTTOM (solid shape): 18.85,37.52 18.85,35.62 18.73,35.49 17.33,35.49 17.07,35.74 17.07,37.65 17.2,37.77 18.6,37.77
N22763812 on BOTTOM (solid shape): 21.52,24.31 21.52,22.15 21.39,22.03 19.74,22.03 19.61,22.15 19.61,24.69 19.74,24.82 21.01,24.82
N22763935 on BOTTOM (solid shape): 41.84,33.46 41.84,32.19 41.59,31.93 39.17,31.93 39.05,32.06 39.05,33.46 39.3,33.71 41.59,33.71
N22764304 on BOTTOM (solid shape): 46.54,39.04 46.54,36.38 46.03,35.87 41.97,35.87 40.7,37.14 38.79,37.14 38.54,37.39 38.54,37.67 39.91,37.67 40.27,38.03 39.91,38.38 38.64,38.38 38.64,39.4 38.92,39.68 45.9,39.68
N22892968 on TOP (solid shape): 74.13,109.87 74.13,108.92 74.1,108.89 73.43,108.89 72.7,109.62 71.27,109.62 71.21,109.68 71.21,109.88 71.26,109.93 74.07,109.93
N23711299 on TOP (solid shape): 207.09,11.8 207.13,11.79 207.14,11.75 207.14,9.14 207.46,8.82 209.24,8.82 209.43,8.63 209.43,5.19 209.28,5.04 208.53,5.04 207.74,5.83 206.88,5.83 206.84,5.85 206.83,5.88 206.83,6.41 205.43,6.41 205.43,5.88 205.41,5.85 205.38,5.83 204.92,5.83 204.67,6.09 204.67,11.75 204.68,11.79 204.72,11.8
N23711331 on TOP (solid shape): 210.52,13.06 210.52,10.6 210.37,10.44 209.86,10.44 209.66,10.65 209.66,11.54 209.33,11.87 207.65,11.87 207.47,12.04 207.47,12.55 207.7,12.78 209.1,12.78 209.51,13.19 210.39,13.19
N46660696 on BOTTOM (solid shape): 87.05,121.21 87.05,120.32 86.92,120.2 85.15,120.2 85.02,120.07 85.02,119.56 84.77,119.31 83.75,119.31 83.62,119.44 83.62,121.09 83.88,121.34 86.92,121.34
N47008006 on TOP (solid shape): 32.19,108.26 33.71,108.26 33.84,108.13 33.84,106.99 33.71,106.86 30.92,106.86 30.79,106.99 30.79,108.89 30.92,109.02 31.43,109.02
N47415217 on TOP (solid shape): 73.65,23.21 73.65,22.49 73.57,22.41 71,22.41 70.91,22.5 70.91,23.18 71,23.28 73.58,23.28
N47415258 on TOP (solid shape): 68.51,27.49 68.51,24.95 68.26,24.69 67.24,24.69 66.99,24.95 66.99,27.69 67,27.73 67.04,27.74 68.26,27.74
N47415272 on TOP (solid shape): 68,14.15 68,10.22 67.64,9.85 65.81,9.85 65.56,10.11 65.56,12.6 65.62,12.66 66.26,12.66 66.3,12.71 66.3,13.98 66.6,14.28 67.87,14.28
N47415370 on TOP (solid shape): 72.38,13.3 72.38,12.76 72.12,12.51 70.27,12.51 70.02,12.76 70.02,13.33 70.19,13.5 72.19,13.5
N47420895 on BOTTOM (solid shape): 88.7,22.33 88.7,21.52 88.58,21.39 87.18,21.39 86.8,21.01 86.8,20.03 86.64,19.87 85.62,19.87 85.53,19.96 85.53,21.52 85.78,21.77 86.06,21.77 87.17,22.88 88.15,22.88
N55155843 on TOP (solid shape): 12.3,75.09 12.3,74.1 12.17,73.97 9.45,73.97 9.33,74.1 9.33,75.04 9.48,75.19 12.2,75.19
N55200533 on TOP (solid shape): 195.38,89.46 195.38,86.16 195.76,85.78 196.4,85.78 196.43,85.76 196.43,85.75 196.57,85.59 196.78,85.53 196.86,85.53 196.89,85.51 196.91,85.47 196.91,84.76 196.89,84.75 196.87,84.73 196.84,84.73 196.62,84.7 196.46,84.54 196.44,84.52 196.41,84.51 195.89,84.51 195.38,84 195.38,80.7 195.26,80.57 193.73,80.57 193.48,80.83 193.48,82.22 193.92,82.67 193.93,82.67 194.02,82.74 194.09,82.84 194.37,83.11 194.37,87.3 193.6,88.07 193.6,89.59 193.86,89.84 195,89.84
N64564191 on TOP (solid shape): 41.33,51.62 41.33,51.24 41.2,51.11 40.57,51.11 40.44,50.98 40.44,50.09 40.32,49.97 39.17,49.97 39.05,50.09 39.05,51.62 39.17,51.74 41.2,51.74

Small or netless copper shapes (teardrops, artwork), in the pictures only: 68 on TOP, 280 on BOTTOM, 2 on IN2

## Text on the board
Ref Des/Silkscreen Bottom: FAN | RTC | H18 | H17 | DDR3L | Support | SODIMM | Only | H19 | HDD | SPK | EDP | IO | SODIMM-Only support DDR3L | WLAN
User.Comments: ZAVC0 | Minjia | LA-B012P | 2014-01-20 | 2015-01-20 | 1.0 | PARTITION_2 | PARTITION_3 | PARTITION_4
Ref Des/Silkscreen Top: TP | LED | KB | KBBL
BODY_CENTER: FIGURE | SIZE | 8.0 | 10.0 | 22.0 | 28.0 | 37.0 | 47.0 | 110.0 | 118.0 | 130.0 | 142.0 | 40.0 | 43.0 | 63.0 | 71.0 | 59.0x24.0 | 63.0x35.0 | 71.0x31.0 | 87.0x24.0 | 102.0x31.0 | 110.0x39.0 | 130.0x110.0 | 189.0x110.0 | DRILL CHART: TOP to BOTTOM | ALL UNITS ARE IN MILS | PLATED | NON-PLATED | QTY | 4198 | 1161 | 19 | 18 | 8 | 9 | 10 | 1 | 3 | 4 | 2 | 5 | 7
COMPVAL_TYPE_BOTTOM: trace Width | Width/Space | L3 | L4 | L5 | L6 | L1 | L2 | LAYER | NAME | STACKUP: 6 LAYER | SB_1_0mm-6L(3mil core 0.5oz)_130731 | 35 ohm | 40 ohm | 45 ohm | THICKNESS=1mm | 50 ohm | 75 ohm | 80 ohm | 83 ohm | 85 ohm | 90 ohm | 100ohm | -TOP | -VCC | -IN1 | -IN2 | -GND | -BOT | 8 | 7.8 | 6.4 | 6.2 | 5.1 | 4.9 | 4 | 4.2 | 5.1/3.5 | 4.9/3.7 | 5.5/7.5 | 4.7/5.2 | 4.5/5.3 | 4.4/5.7 | 4.4/8.6 | 4.5/8.5 | 3.6/11
User.22: 8.00 | 60.50 | 58.55 | 4.00 | 0.00 | 118.80 | 94.25 | 105.00 | SCALE | 1.000 | 190.70 | 183.75 | 182.90 | 111.65 | 84.10 | 10.00 | TOP VIEW
User.23: 74.85 | 19.80 | 4.00 | 0.00 | 113.51 | 202.65 | 178.75 | 23.10 | 10.00 | BOTTOM VIEW
User.24: GND | +5VALW | +1.35V_MEM_GFX | +3VS | +3VALW | GNDA | +VGA_CORE | +CPU_CORE | +1.05VS_PCH | +LAN_VDD33
User.27: 191.65 | 182.90 | 5.11 | 2.30 | 0.85 | 0.00 | 10.00 | 16.82 | 4.00 | 29.10 | 57.05 | 75.25 | 81.90 | 94.25 | 102.00 | 6.50 | 58.55 | 60.50 | 185.75 | 112.65 | 84.10 | 2.65
User.28: 19.80 | 46.75 | 71.10 | 74.85 | 84.06 | 107.45 | 202.65 | 108.25 | 95.85 | 0.00 | 10.00 | 197.35 | 178.75 | 177.00 | 31.93 | 23.94 | 4.20 | 4.00 | 60.98 | 104.75 | 105.80
User.29: 0.00 | 10.00 | 4.00 | 118.80
User.31: 182.30 | 176.60 | 170.60 | 0.50 | 0.05 | 118.07 | 99.80 | 39.40 | 22.67 | 8.90 | 6.00 | 0.00 | 108.80 | 12.30 | 22.40 | 27.45 | 37.70 | 49.00 | 114.80 | 96.50 | 86.70 | 11.97 | 26.70 | 58.23 | 61.00 | 109.00 | 115.30 | 182.60 | 162.73 | 121.60 | 103.40 | 38.60 | 21.40 | 9.40 | 4.90
User.32: {\Fgdt;n}\Ftxt;8.00 | {\Fgdt;n}\Ftxt;2.80 | 2.80 | {\Fgdt;n}\Ftxt;3.30 | {\Fgdt;n}\Ftxt;6.00 | {\Fgdt;n}\Ftxt;3.60 | {\Fgdt;n}\Ftxt;7.00 | {\Fgdt;n}\Ftxt;9.00 | 3.30 | 5.50 | {\Fgdt;n}\Ftxt;8.55 | 4.80
User.37: TP | 191.65 | 182.90 | 5.11 | 2.30 | 0.85 | 0.00 | 10.00 | 16.82 | 4.00 | 29.10 | 57.05 | 75.25 | 81.90 | 94.25 | 102.00 | 6.50 | 58.55 | 60.50 | 185.75 | 112.65 | 84.10 | 2.65
User.38: TP | V-CUT | 19.80 | 46.75 | 71.10 | 74.85 | 84.06 | 107.45 | 202.65 | 108.25 | 95.85 | 0.00 | 10.00 | 197.35 | 178.75 | 177.00 | 31.93 | 23.94 | 4.20 | 4.00 | 60.98 | 104.75 | 105.80
User.39: TP | V-CUT | 0.00 | 10.00 | 4.00 | 118.80
User.40: TP | V-CUT
User.41: 182.30 | 176.60 | 170.60 | 0.50 | 0.05 | 118.07 | 99.80 | 39.40 | 22.67 | 8.90 | 6.00 | 0.00 | 108.80 | 12.30 | 22.40 | 27.45 | 37.70 | 49.00 | 114.80 | 96.50 | 86.70 | 11.97 | 26.70 | 58.23 | 61.00 | 109.00 | 115.30 | 182.60 | 162.73 | 121.60 | 103.40 | 38.60 | 21.40 | 9.40 | 4.90
User.42: {\Fgdt;n}\Ftxt;8.00 | {\Fgdt;n}\Ftxt;2.80 | 2.80 | {\Fgdt;n}\Ftxt;3.30 | {\Fgdt;n}\Ftxt;6.00 | {\Fgdt;n}\Ftxt;3.60 | {\Fgdt;n}\Ftxt;7.00 | {\Fgdt;n}\Ftxt;9.00 | 3.30 | 5.50 | {\Fgdt;n}\Ftxt;8.55 | 4.80
User.45: TP | V-CUT | 191.65 | 182.30 | 182.90 | 176.60 | 170.60 | 0.50 | 0.05 | 118.07 | 99.80 | 39.40 | 22.67 | 5.11 | 8.90 | 2.30 | 6.00 | 0.85 | 0.00 | 10.00 | 4.00 | 108.80 | 12.30 | 22.40 | 27.45 | 37.70 | 49.00 | 114.80 | 118.80 | 96.50 | 86.70 | 16.82 | 29.10 | 57.05 | 75.25 | 81.90 | 94.25 | 102.00 | 19.80 | 46.75 | 71.10 | 74.85 | 84.06 | 107.45 | 202.65 | {\Fgdt;n}\Ftxt;8.00 | {\Fgdt;n}\Ftxt;2.80 | 2.80 | {\Fgdt;n}\Ftxt;3.30 | {\Fgdt;n}\Ftxt;6.00 | {\Fgdt;n}\Ftxt;3.60 | 108.25 | {\Fgdt;n}\Ftxt;7.00 | 95.85 | {\Fgdt;n}\Ftxt;9.00 | 122.80 | 214.40 | 6.50 | 11.97 | 26.70 | 58.55 | 58.23 | 60.50 | 61.00 | 109.00 | 115.30 | 185.75 | 182.60 | 162.73 | 121.60 | 112.65 | 103.40 | 84.10 | 38.60 | 21.40 | 9.40 | 2.65 | 4.90 | 197.35 | 178.75 | 177.00 | 3.30 | 31.93 | 23.94 | 5.50 | {\Fgdt;n}\Ftxt;8.55 | 4.20 | 4.80 | 60.98 | 104.75 | 105.80
